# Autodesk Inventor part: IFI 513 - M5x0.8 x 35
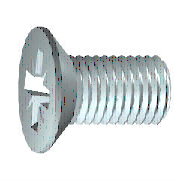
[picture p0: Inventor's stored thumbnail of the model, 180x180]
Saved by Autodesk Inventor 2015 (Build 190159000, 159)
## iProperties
IsCustomPart: 1
Created: 2014-02
Part Number: IFI 513 - M5x0.8 x 35
Material: Steel, Mild
Description: Cross Recessed Flat Countersunk Head Machine Screw - Type IA - Metric
Document SubType Name: Modeling
Standard: IFI 513
Designer: rsheridan
Standards Organization: ANSI
Language: en-US
Size Designation: M5x0.8 x 35
Categories: <MemberInstance><Categories><Category DisplayName="Fasteners" InternalName="e4da775c-781d-43d5-af7c-5136215cf5a6" Mnemonic="FSTN"><Category DisplayName="Bolts"
Density: 1 g/cm^3
Appearance: Semi-Polished
Author: rsheridan
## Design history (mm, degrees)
body "Solid1"
sketch "Sketch1"
  geometry: L1 (3.46, 0)-(35, 0); L2 (35, 0)-(35, 2.5); L3 (35, 2.5)-(4.7, 2.5); L4 (4.7, 2.5)-(4.209, 2.5); L5 (4.209, 2.5)-(2.7, 2.5); L6 (0, 4.45)-(0, 2.575); L7 (0, 2.575)-(2.845, 1.156); L8 (2.845, 1.156)-(3.46, 0); L9 (-7, 0)-(42, 0) reference; L10 (0, -0.89)-(0, 5.34) reference; L11 (0, 4.45)-(0.75, 4.45); L12 (0.75, 4.45)-(2.7, 2.5); L13 (4.7, 2.5)-(2.7, 2.5)
  constraints: 22 end point, 3 parallel, 3 perpendicular, 2 collinear, 1 horizontal, 1 point on line
  dimensions: "d1" = 30.3 distance of L2.end L3.end (= GEL); "d2" = 5 diameter of L3 L1 (= GD); "d3" = 5 diameter of L5 L1 (= BDM); "d4" = 5.15 diameter of L6.end L1 (= SDM); "d5" = 26.5 deg angle of L7 L1; "d6" = 62 deg angle of L8 L1; "d7" = 3.46 distance from line of L1.start L6 (= INTI); "d8" = 0.49076 distance of L4.end L3.end (= GAL); "d18" = 8.9 diameter of L11 L1 (= KOD); "d19" = 45 deg angle of L12 L1 (= 0.5 x SEWI); "d21" = 35 distance between parallel lines of L2 L6 (= NLG); "d29" = 2.7 distance from line of L5.end L6 (= KOH)
revolve "Body" stored, may be unused: angle "d16" = 90 deg
sketch "Sketch2"
  geometry: L1 (0, 2.575)-(0, 0); L2 (0, 0)-(2.575, 0); L3 (0, 0)-(1.821, 1.821); L4 (0.52, 2.522)-(0.348, 1.24); L5 (2.522, 0.52)-(1.24, 0.348); L6 (0, -6.23)-(0, 6.23) reference; L7 (-6.23, 0)-(6.23, 0) reference; L8 (2.522, -0.52)-(1.24, -0.348); L9 (0.52, -2.522)-(0.348, -1.24); L10 (-0.52, -2.522)-(-0.348, -1.24); L11 (-2.522, -0.52)-(-1.24, -0.348); L12 (-2.522, 0.52)-(-1.24, 0.348); L13 (-0.52, 2.522)-(-0.348, 1.24); A1 r 1.03 centre (0, 0) between (1.03, 0) and (0, 1.03); A2 r 1.288 centre (0, 0) between (1.288, 0) and (0, 1.288); A3 r 2.575 centre (0, 0) between (2.522, 0.52) and (0.52, 2.522); A4 r 0.351 centre (0.696, 1.193) between (0.348, 1.24) and (0.945, 0.945); A5 r 0.351 centre (1.193, 0.696) between (0.945, 0.945) and (1.24, 0.348); A6 r 2.575 centre (0, 0) between (0.52, 2.522) and (0, 2.575); A7 r 2.575 centre (0, 0) between (2.575, 0) and (2.522, 0.52); A8 r 2.575 centre (0, 0) between (0, -2.575) and (0.52, -2.522); A9 r 2.575 centre (0, 0) between (0.52, -2.522) and (2.522, -0.52); A10 r 2.575 centre (0, 0) between (2.522, -0.52) and (2.575, 0); A11 r 0.351 centre (0.696, -1.193) between (0.945, -0.945) and (0.348, -1.24); A12 r 0.351 centre (1.193, -0.696) between (1.24, -0.348) and (0.945, -0.945); A13 r 2.575 centre (0, 0) between (0, 2.575) and (-0.52, 2.522); A14 r 2.575 centre (0, 0) between (-0.52, 2.522) and (-2.522, 0.52); A15 r 2.575 centre (0, 0) between (-2.522, 0.52) and (-2.575, 0); A16 r 2.575 centre (0, 0) between (-2.575, 0) and (-2.522, -0.52); A17 r 2.575 centre (0, 0) between (-2.522, -0.52) and (-0.52, -2.522); A18 r 2.575 centre (0, 0) between (-0.52, -2.522) and (0, -2.575); A19 r 0.351 centre (-0.696, -1.193) between (-0.348, -1.24) and (-0.945, -0.945); A20 r 0.351 centre (-1.193, -0.696) between (-0.945, -0.945) and (-1.24, -0.348); A21 r 0.351 centre (-0.696, 1.193) between (-0.945, 0.945) and (-0.348, 1.24); A22 r 0.351 centre (-1.193, 0.696) between (-1.24, 0.348) and (-0.945, 0.945); 3 further points
  constraints: 49 point on circle, 29 symmetric about line, 22 centre point, 22 end point, 11 coincident, 3 point on line, 3 tangent, 2 collinear, 2 midpoint, 1 perpendicular, 1 vertical, 23 other
  dimensions: "d22" = 2.06 diameter of A1 (= 0.4 x SDM); "d23" = 2.575 diameter of A2 (= 0.5 x SDM); "d24" = 5.15 diameter of A3 (= SDM); "d25" = 45 deg angle of L3 L2; "d26" = 0.52 distance from line of L4.start L1 (= 0.5 x SBR)
extrude "Slot" join sketch "Sketch2" taper "d27" = 5 deg; stored distance "d79" = 25.4
fillet "Fillet1" dims "d28" = 0.208 (= 0.2 x SBR)
sketch "Sketch3"
  geometry: L1 (0, 0)-(-1.821, 1.821); L2 (0, -6.23)-(0, 6.23) reference; L3 (-6.23, 0)-(6.23, 0) reference; L4 (-1.821, 1.821)-(-0.26, 0); L5 (0, 0)-(1.821, 1.821); L6 (0, 0)-(1.821, -1.821); L7 (0, 0)-(-1.821, -1.821); L8 (-1.821, -1.821)-(0, -0.26); L9 (1.821, -1.821)-(0.26, 0); L10 (1.821, 1.821)-(0, 0.26); L11 (-1.821, 1.821)-(0, 0.26); L12 (-0.26, 0)-(-1.821, -1.821); L13 (0, -0.26)-(1.821, -1.821); L14 (0.26, 0)-(1.821, 1.821); A1 r 0.26 centre (0, 0) between (-0.26, 0) and (0, -0.26); A2 r 2.575 centre (0, 0) between (-2.522, 0.52) and (-2.522, -0.52) reference; A3 r 2.575 centre (0, 0) between (-2.522, -0.52) and (-1.821, 1.821)
  constraints: 24 end point, 6 point on circle, 4 point on line, 3 symmetric about line, 2 centre point, 1 coincident, 3 other
  dimensions: "d10" = 45 deg angle of L1 L2; "d11" = 0.52 diameter of A1 (= 0.5 x SBR)
extrude "Star Cut" cut sketch "Sketch3" distance "d12" = 2.7 (= KOH); taper "d13" = -30 deg
feature "Thread" dims "d14" = 30.3 (= GEL), "d15" = 0
chamfer "Chamfer1" distance "d32" = 0.7 (= -0.5 x SPD + 0.5 x GD); stored, may be unused: second distance "d33" = 0.49086 (computed from GUL), angle "d87" = 45 deg
workplane "Work Plane2"
other parameters: "NLG" = 35 [user parameter; used in 1 equation term], "GEL" = 30.3 [user parameter; used in 2 equation terms], "GAL" = 0.49076 (= 0.61345 x PTC) [user parameter; used in 1 equation term], "SPD" = 3.6 [user parameter; used in 1 equation term], "KOD" = 8.9 [user parameter; used in 1 equation term], "KOH" = 2.7 [user parameter; used in 2 equation terms], "SBR" = 1.04 [user parameter; used in 3 equation terms], "INTI" = 3.46 [user parameter; used in 1 equation term], "SDM" = 5.15 [user parameter; used in 5 equation terms], "GD" = 5 (= NND) [user parameter; used in 2 equation terms], "BDM" = 5 [user parameter; used in 1 equation term], "SEWI" = 90 deg [user parameter; used in 1 equation term], "d9" = 5.15 (= SDM), "GUL" = 0.49076 (= 0.61345 x PTC) [user parameter; used in 1 equation term], "d30" = 0, "d91" = 0, "d92" = 0, "TOA" = 30 deg [user parameter], "KODMAX" = 10.4 [user parameter], "EPV" = 5.20001 [user parameter], "THREADDIA" = 5 [user parameter; used in 1 equation term], "TPU" = 12.5 (computed from PTC) [user parameter], "PTC" = 0.8 [user parameter; used in 4 equation terms], "NND" = 5 [user parameter; used in 1 equation term], "GD1" = 4.01848 (= THREADDIA - 1.2269 x PTC) [user parameter]
